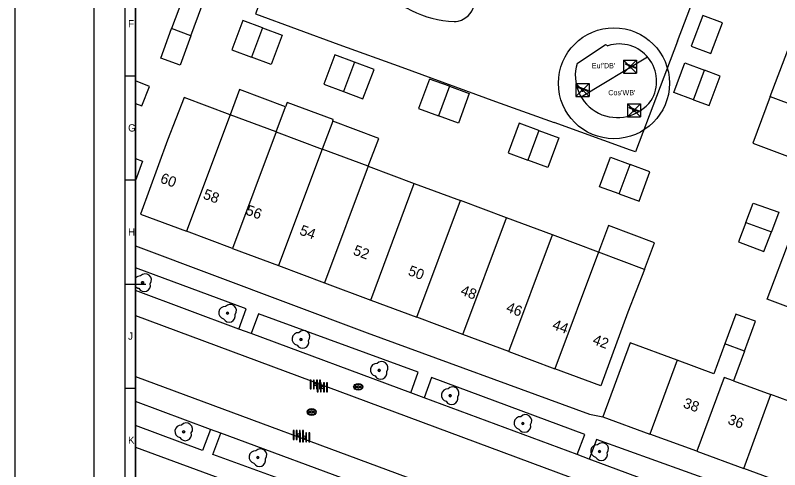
# Model space of a CAD drawing. Extents: x 192664 to 192925, y 446334 to 446521.
# Drawn here: x 192664.2 to 192737.6, y 446409.8 to 446453.5 of the extents above; entities that cross this region are included whole.
import ezdxf

# ---------------------------------------------------------------- set-up
doc = ezdxf.new("R2010")
doc.units = 0
for name, color, linetype in [('1010 viewport', 7, 'Continuous'), ('B-GV-KG-GRENS_WERKGRENS-G', 7, 'Continuous'), ('boom', 7, 'Continuous'), ('grens maaiveld', 7, 'Continuous'), ('huisnummerreeks BGT', 7, 'Continuous'), ('inspectie-   rioolput', 7, 'Continuous'), ('kant open verharding', 7, 'Continuous'), ('kant verharding', 7, 'Continuous'), ('kolk', 7, 'Continuous'), ('Luifel', 7, 'Continuous'), ('N-GV-GR-BEPLANTING-G', 7, 'Continuous'), ('pand op maaiveld vlak', 7, 'Continuous'), ('speelvoorziening', 7, 'Continuous'), ('TEKST', 7, 'Continuous'), ('V-GV-IE-MEUBILAIR_WEGMEUBILAIR_SPEELTOESTEL-G', 7, 'Continuous'), ('verkeerseiland - berm', 7, 'Continuous'), ('X-XX-AL-TEKENBLAD-S', 7, 'Continuous'), ('X-XX-AL-TEKENBLAD_KADER-G', 7, 'Continuous')]:
    doc.layers.add(name, color=color, linetype=linetype)

msp = doc.modelspace()

# ---------------------------------------------------------------- linework, layer by layer
at = {"layer": '1010 viewport'}
msp.add_lwpolyline([(192675.743, 446509.756), (192860.643, 446509.756), (192860.643, 446345.556), (192675.743, 446345.556)], close=True, dxfattribs=at)
at = {"layer": 'B-GV-KG-GRENS_WERKGRENS-G'}
msp.add_circle((192721.667, 446446.943), 5.327, dxfattribs=at)
at = {"layer": 'boom'}
msp.add_line((192675.743, 446428.235), (192675.743, 446427.429), dxfattribs=at)
for centre in [(192676.438, 446427.782), (192684.588, 446424.849), (192691.63, 446422.331), (192699.133, 446419.361), (192705.949, 446416.928), (192712.93, 446414.262), (192680.38, 446413.459), (192720.289, 446411.56), (192687.499, 446410.984)]:
    msp.add_circle(centre, 0.1, dxfattribs=at)
for centre, radius, start, end in [((192676.188, 446427.832), 0.6, 85.13702, 137.81973), ((192676.688, 446428.032), 0.6, 323.54458, 138.4658), ((192676.588, 446427.532), 0.6, 208.50578, 13.83556), ((192676.438, 446427.782), 0.1, 0, 180), ((192676.438, 446427.782), 0.1, 180, 0), ((192676.188, 446427.832), 0.6, 222.18027, 257.75442), ((192684.338, 446424.899), 0.6, 85.13702, 257.75442), ((192684.838, 446425.099), 0.6, 323.54458, 138.4658), ((192684.738, 446424.599), 0.6, 208.50578, 13.83556), ((192684.588, 446424.849), 0.1, 0, 180), ((192684.588, 446424.849), 0.1, 180, 0), ((192691.38, 446422.381), 0.6, 85.13702, 257.75442), ((192691.88, 446422.581), 0.6, 323.54458, 138.4658), ((192691.78, 446422.081), 0.6, 208.50578, 13.83556), ((192691.63, 446422.331), 0.1, 0, 180), ((192691.63, 446422.331), 0.1, 180, 0), ((192698.883, 446419.411), 0.6, 85.13702, 257.75442), ((192699.383, 446419.611), 0.6, 323.54458, 138.4658), ((192699.283, 446419.111), 0.6, 208.50578, 13.83556), ((192699.133, 446419.361), 0.1, 0, 180), ((192699.133, 446419.361), 0.1, 180, 0), ((192705.699, 446416.978), 0.6, 85.13702, 257.75442), ((192706.199, 446417.178), 0.6, 323.54458, 138.4658), ((192706.099, 446416.678), 0.6, 208.50578, 13.83556), ((192705.949, 446416.928), 0.1, 0, 180), ((192705.949, 446416.928), 0.1, 180, 0), ((192712.68, 446414.312), 0.6, 85.13702, 257.75442), ((192713.18, 446414.512), 0.6, 323.54458, 138.4658), ((192680.13, 446413.509), 0.6, 85.13702, 257.75442), ((192680.63, 446413.709), 0.6, 323.54458, 138.4658), ((192713.08, 446414.012), 0.6, 208.50578, 13.83556), ((192712.93, 446414.262), 0.1, 0, 180), ((192712.93, 446414.262), 0.1, 180, 0), ((192680.53, 446413.209), 0.6, 208.50578, 13.83556), ((192680.38, 446413.459), 0.1, 0, 180), ((192680.38, 446413.459), 0.1, 180, 0), ((192720.039, 446411.61), 0.6, 85.13702, 257.75442), ((192720.539, 446411.81), 0.6, 323.54458, 138.4658), ((192687.249, 446411.034), 0.6, 85.13702, 257.75442), ((192687.749, 446411.234), 0.6, 323.54458, 138.4658), ((192720.439, 446411.31), 0.6, 208.50578, 13.83556), ((192720.289, 446411.56), 0.1, 0, 180), ((192720.289, 446411.56), 0.1, 180, 0), ((192687.649, 446410.734), 0.6, 208.50578, 13.83556), ((192687.499, 446410.984), 0.1, 0, 180), ((192687.499, 446410.984), 0.1, 180, 0)]:
    msp.add_arc(centre, radius, start, end, dxfattribs=at)
at = {"layer": 'grens maaiveld'}
for p, q in [((192727.776, 446450.988), (192734.733, 446469.332)), ((192695.28, 446450.68), (192701.299, 446448.474))]:
    msp.add_line(p, q, dxfattribs=at)
for points in [[(192706.331, 446452.863), (192706.518, 446452.877), (192706.732, 446452.916), (192707.023, 446453.007), (192707.362, 446453.181), (192707.672, 446453.423), (192707.87, 446453.641), (192708.021, 446453.863), (192708.159, 446454.143), (192708.26, 446454.473), (192708.295, 446454.703), (192708.29, 446455.149), (192708.241, 446455.406), (192708.137, 446455.709), (192707.986, 446455.995), (192707.816, 446456.224), (192707.394, 446456.89), (192705.222, 446458.158), (192705.296, 446459.943), (192704.312, 446461.578), (192703.272, 446461.519), (192701.368, 446465.65), (192700.45, 446467.928), (192697.225, 446464.769)], [(192691.747, 446465.52), (192687.282, 446453.612), (192695.28, 446450.68)], [(192727.776, 446450.988), (192723.743, 446440.355), (192723.261, 446440.509), (192715.923, 446443.165)], [(192718.128, 446448.834), (192720.866, 446450.656), (192721.084, 446450.551)], [(192701.299, 446448.474), (192710.291, 446445.203), (192715.923, 446443.165)]]:
    msp.add_lwpolyline(points, dxfattribs=at)
for centre, radius, start, end in [((192706.69, 446462.573), 9.716, 166.93585, 267.88344), ((192722.168, 446447.137), 3.582, 328.76282, 107.61496), ((192721.99, 446447.676), 4.031, 163.30738, 323.51736)]:
    msp.add_arc(centre, radius, start, end, dxfattribs=at)
at = {"layer": 'inspectie-   rioolput'}
for p, q in [((192697.037, 446417.818), (192696.88, 446417.818)), ((192696.88, 446417.742), (192697.037, 446417.742)), ((192697.38, 446417.818), (192697.223, 446417.818)), ((192697.223, 446417.742), (192697.38, 446417.742)), ((192692.564, 446415.408), (192692.407, 446415.408)), ((192692.407, 446415.333), (192692.564, 446415.333)), ((192692.907, 446415.408), (192692.75, 446415.408)), ((192692.75, 446415.333), (192692.907, 446415.333))]:
    msp.add_line(p, q, dxfattribs=at)
for centre, radius, start, end in [((192696.88, 446417.78), 0.0375, 90, 270), ((192697.13, 446417.78), 0.1, 0, 180), ((192697.13, 446417.78), 0.1, 157.97569, 180), ((192697.13, 446417.78), 0.1, 180, 202.02431), ((192697.13, 446417.78), 0.1, 180, 0), ((192697.13, 446417.78), 0.1, 0, 22.02431), ((192697.13, 446417.78), 0.1, 337.97569, 0), ((192697.38, 446417.78), 0.0375, 270, 90), ((192692.407, 446415.37), 0.0375, 90, 270), ((192692.657, 446415.37), 0.1, 0, 180), ((192692.657, 446415.37), 0.1, 157.97569, 180), ((192692.657, 446415.37), 0.1, 180, 202.02431), ((192692.657, 446415.37), 0.1, 180, 0), ((192692.657, 446415.37), 0.1, 0, 22.02431), ((192692.657, 446415.37), 0.1, 337.97569, 0), ((192692.907, 446415.37), 0.0375, 270, 90)]:
    msp.add_arc(centre, radius, start, end, dxfattribs=at)
for centre, major_axis, ratio in [((192697.13, 446417.78), (-0.442, 0), 0.73911), ((192697.13, 446417.78), (-0.392, 0), 0.689655), ((192692.657, 446415.37), (-0.442, 0), 0.73911), ((192692.657, 446415.37), (-0.392, 0), 0.689655)]:
    msp.add_ellipse(centre, major_axis=major_axis, ratio=ratio, dxfattribs=at)
at = {"layer": 'kant open verharding'}
for points in [[(192675.743, 446431.332), (192697.987, 446422.959), (192719.324, 446415.141), (192720.614, 446414.897)], [(192675.743, 446411.995), (192713.029, 446398.263), (192714.204, 446397.83), (192714.097, 446397.514)]]:
    msp.add_lwpolyline(points, dxfattribs=at)
at = {"layer": 'kant verharding'}
for p, q in [((192675.743, 446424.623), (192733.082, 446403.313)), ((192686.85, 446422.89), (192685.668, 446423.329)), ((192675.743, 446418.762), (192731.114, 446398.266)), ((192703.446, 446416.734), (192702.166, 446417.209)), ((192683.929, 446413.333), (192682.95, 446413.694)), ((192719.304, 446410.835), (192718.14, 446411.268))]:
    msp.add_line(p, q, dxfattribs=at)
at = {"layer": 'kolk'}
for points in [[(192692.616, 446418.006), (192692.616, 446418.431), (192692.531, 446418.431), (192692.531, 446418.006), (192692.531, 446417.581), (192692.616, 446417.581)], [(192692.914, 446418.006), (192692.914, 446418.431), (192692.829, 446418.431), (192692.829, 446418.006), (192692.829, 446417.581), (192692.914, 446417.581)], [(192693.211, 446418.006), (192693.211, 446418.431), (192693.126, 446418.431), (192693.126, 446418.006), (192693.126, 446417.581), (192693.211, 446417.581)], [(192693.282, 446417.729), (192693.282, 446418.154), (192693.197, 446418.154), (192693.197, 446417.729), (192693.197, 446417.304), (192693.282, 446417.304)], [(192693.509, 446418.006), (192693.509, 446418.431), (192693.424, 446418.431), (192693.424, 446418.006), (192693.424, 446417.581), (192693.509, 446417.581)], [(192693.58, 446417.729), (192693.58, 446418.154), (192693.495, 446418.154), (192693.495, 446417.729), (192693.495, 446417.304), (192693.58, 446417.304)], [(192693.877, 446417.729), (192693.877, 446418.154), (192693.792, 446418.154), (192693.792, 446417.729), (192693.792, 446417.304), (192693.877, 446417.304)], [(192694.175, 446417.729), (192694.175, 446418.154), (192694.09, 446418.154), (192694.09, 446417.729), (192694.09, 446417.304), (192694.175, 446417.304)], [(192690.973, 446413.16), (192690.973, 446413.585), (192690.888, 446413.585), (192690.888, 446413.16), (192690.888, 446412.735), (192690.973, 446412.735)], [(192691.271, 446413.16), (192691.271, 446413.585), (192691.186, 446413.585), (192691.186, 446413.16), (192691.186, 446412.735), (192691.271, 446412.735)], [(192691.568, 446413.16), (192691.568, 446413.585), (192691.483, 446413.585), (192691.483, 446413.16), (192691.483, 446412.735), (192691.568, 446412.735)], [(192691.583, 446412.932), (192691.583, 446413.357), (192691.498, 446413.357), (192691.498, 446412.932), (192691.498, 446412.507), (192691.583, 446412.507)], [(192691.866, 446413.16), (192691.866, 446413.585), (192691.781, 446413.585), (192691.781, 446413.16), (192691.781, 446412.735), (192691.866, 446412.735)], [(192691.881, 446412.932), (192691.881, 446413.357), (192691.796, 446413.357), (192691.796, 446412.932), (192691.796, 446412.507), (192691.881, 446412.507)], [(192692.178, 446412.932), (192692.178, 446413.357), (192692.093, 446413.357), (192692.093, 446412.932), (192692.093, 446412.507), (192692.178, 446412.507)], [(192692.476, 446412.932), (192692.476, 446413.357), (192692.391, 446413.357), (192692.391, 446412.932), (192692.391, 446412.507), (192692.476, 446412.507)]]:
    msp.add_lwpolyline(points, close=True, dxfattribs=at)
for centre, start, end in [((192693.02, 446418.006), 0, 180), ((192693.02, 446418.006), 180, 0), ((192693.686, 446417.729), 0, 180), ((192693.686, 446417.729), 180, 0), ((192691.377, 446413.16), 0, 180), ((192691.377, 446413.16), 180, 0), ((192691.987, 446412.932), 0, 180), ((192691.987, 446412.932), 180, 0)]:
    msp.add_arc(centre, 0.1, start, end, dxfattribs=at)
at = {"layer": 'Luifel'}
for p, q in [((192689.258, 446442.274), (192690.161, 446444.691)), ((192694.676, 446443.3), (192693.675, 446440.623))]:
    msp.add_line(p, q, dxfattribs=at)
for points in [[(192729.308, 446445.356), (192730.801, 446444.796), (192731.861, 446447.624), (192730.368, 446448.184)], [(192690.161, 446444.691), (192685.743, 446446.341), (192684.84, 446443.924)], [(192694.676, 446443.3), (192694.73, 446443.445), (192690.312, 446445.096), (192690.161, 446444.691)], [(192698.093, 446438.972), (192699.094, 446441.649), (192694.676, 446443.3)], [(192724.599, 446429.067), (192725.554, 446431.622), (192721.136, 446433.273), (192720.181, 446430.718)]]:
    msp.add_lwpolyline(points, dxfattribs=at)
at = {"layer": 'N-GV-GR-BEPLANTING-G'}
msp.add_line((192718.512, 446445.637), (192724.889, 446449.467), dxfattribs=at)
msp.add_lwpolyline([(192718.128, 446448.834), (192720.866, 446450.656), (192721.084, 446450.551)], dxfattribs=at)
for centre, radius, start, end in [((192722.168, 446447.137), 3.582, 328.76282, 107.61496), ((192721.99, 446447.676), 4.031, 163.30738, 323.51736)]:
    msp.add_arc(centre, radius, start, end, dxfattribs=at)
at = {"layer": 'pand op maaiveld vlak'}
for p, q in [((192681.074, 446451.51), (192679.224, 446452.192)), ((192687.949, 446452.262), (192686.895, 446449.442)), ((192736.66, 446445.654), (192738.338, 446450.129)), ((192696.761, 446448.973), (192695.704, 446446.144)), ((192729.308, 446445.356), (192730.368, 446448.184)), ((192705.871, 446446.648), (192704.828, 446443.814)), ((192736.66, 446445.654), (192747.878, 446441.449)), ((192684.84, 446443.924), (192680.653, 446432.721)), ((192689.258, 446442.274), (192684.84, 446443.924)), ((192689.258, 446442.274), (192685.071, 446431.07)), ((192689.258, 446442.274), (192693.675, 446440.623)), ((192714.47, 446442.392), (192713.417, 446439.561)), ((192693.675, 446440.623), (192689.489, 446429.42)), ((192698.093, 446438.972), (192693.675, 446440.623)), ((192698.093, 446438.972), (192693.906, 446427.769)), ((192698.093, 446438.972), (192702.51, 446437.321)), ((192722.176, 446436.304), (192723.223, 446439.137)), ((192698.324, 446426.118), (192702.51, 446437.321)), ((192702.51, 446437.321), (192706.928, 446435.671)), ((192702.742, 446424.467), (192706.928, 446435.671)), ((192711.346, 446434.02), (192706.928, 446435.671)), ((192707.159, 446422.816), (192711.346, 446434.02)), ((192715.763, 446432.369), (192711.346, 446434.02)), ((192734.324, 446433.557), (192736.775, 446432.672)), ((192685.071, 446431.07), (192680.653, 446432.721)), ((192711.577, 446421.166), (192715.763, 446432.369)), ((192720.181, 446430.718), (192715.763, 446432.369)), ((192685.071, 446431.07), (192689.489, 446429.42)), ((192720.181, 446430.718), (192715.995, 446419.515)), ((192724.599, 446429.067), (192720.181, 446430.718)), ((192689.489, 446429.42), (192693.906, 446427.769)), ((192693.906, 446427.769), (192698.324, 446426.118)), ((192698.324, 446426.118), (192702.742, 446424.467)), ((192707.159, 446422.816), (192702.742, 446424.467)), ((192711.577, 446421.166), (192707.159, 446422.816)), ((192734.182, 446421.216), (192732.296, 446421.908)), ((192711.577, 446421.166), (192715.995, 446419.515)), ((192734.182, 446421.216), (192733.13, 446418.353)), ((192727.725, 446420.338), (192725.118, 446413.242)), ((192733.13, 446418.353), (192736.734, 446417.029)), ((192734.126, 446409.932), (192736.734, 446417.029)), ((192741.127, 446415.414), (192736.734, 446417.029)), ((192720.614, 446414.897), (192725.118, 446413.242)), ((192729.622, 446411.587), (192725.118, 446413.242)), ((192729.622, 446411.587), (192734.126, 446409.932))]:
    msp.add_line(p, q, dxfattribs=at)
for points in [[(192681.074, 446451.51), (192682.119, 446454.348), (192680.269, 446455.029), (192679.224, 446452.192)], [(192729.085, 446450.517), (192730.979, 446449.814), (192732.074, 446452.735), (192730.18, 446453.439), (192729.085, 446450.517)], [(192687.949, 446452.262), (192686.068, 446452.972), (192685.011, 446450.143), (192686.895, 446449.442)], [(192681.074, 446451.51), (192680.029, 446448.672), (192678.178, 446449.354), (192679.224, 446452.192)], [(192687.949, 446452.262), (192689.829, 446451.552), (192688.778, 446448.741), (192686.895, 446449.442)], [(192696.761, 446448.973), (192694.879, 446449.681), (192693.822, 446446.852), (192695.704, 446446.144)], [(192695.704, 446446.144), (192697.585, 446445.436), (192698.642, 446448.265), (192696.761, 446448.973)], [(192729.308, 446445.356), (192727.415, 446446.06), (192728.475, 446448.888), (192730.368, 446448.184)], [(192675.743, 446445.002), (192676.376, 446444.757), (192677.105, 446446.641), (192675.743, 446447.168)], [(192705.871, 446446.648), (192703.964, 446447.349), (192702.921, 446444.515), (192704.828, 446443.814)], [(192705.871, 446446.648), (192707.778, 446445.946), (192706.735, 446443.112), (192704.828, 446443.814)], [(192684.84, 446443.924), (192680.423, 446445.575), (192678.816, 446441.474), (192676.236, 446434.372), (192680.653, 446432.721)], [(192736.66, 446445.654), (192734.983, 446441.178), (192739.086, 446439.641), (192746.201, 446436.974), (192747.878, 446441.449)], [(192714.47, 446442.392), (192712.567, 446443.096), (192711.511, 446440.267), (192713.417, 446439.561)], [(192714.47, 446442.392), (192716.372, 446441.687), (192715.323, 446438.855), (192713.417, 446439.561)], [(192675.743, 446439.714), (192676.434, 446439.457), (192675.743, 446437.601)], [(192722.176, 446436.304), (192720.279, 446437.005), (192721.326, 446439.838), (192723.223, 446439.137)], [(192722.176, 446436.304), (192724.072, 446435.603), (192725.119, 446438.436), (192723.223, 446439.137)], [(192734.324, 446433.557), (192735.013, 446435.41), (192737.504, 446434.553), (192736.775, 446432.672)], [(192734.324, 446433.557), (192733.634, 446431.703), (192736.045, 446430.79), (192736.775, 446432.672)], [(192744.037, 446423.324), (192736.376, 446426.21), (192738.567, 446432.027)], [(192724.599, 446429.067), (192722.99, 446424.96), (192720.412, 446417.864), (192715.995, 446419.515)], [(192734.182, 446421.216), (192735.234, 446424.078), (192734.332, 446424.409), (192733.348, 446424.771), (192732.296, 446421.908)], [(192727.725, 446420.338), (192723.221, 446421.993), (192720.614, 446414.897)], [(192732.296, 446421.908), (192731.243, 446419.044), (192727.725, 446420.338)], [(192733.13, 446418.353), (192732.229, 446418.684), (192729.622, 446411.587)], [(192738.776, 446408.675), (192738.63, 446408.277), (192734.126, 446409.932)]]:
    msp.add_lwpolyline(points, dxfattribs=at)
at = {"layer": 'speelvoorziening'}
for p, q in [((192722.794, 446448.767), (192723.156, 446448.627)), ((192723.737, 446448.466), (192722.816, 446448.822)), ((192723.336, 446448.557), (192723.716, 446448.41)), ((192718.222, 446446.547), (192718.584, 446446.407)), ((192719.165, 446446.246), (192718.244, 446446.602)), ((192718.764, 446446.337), (192719.144, 446446.19)), ((192723.149, 446444.575), (192723.511, 446444.435)), ((192724.092, 446444.274), (192723.171, 446444.63)), ((192723.691, 446444.365), (192724.071, 446444.218))]:
    msp.add_line(p, q, dxfattribs=at)
for centre in [(192723.221, 446448.527), (192718.649, 446446.307), (192723.576, 446444.335)]:
    msp.add_circle(centre, 0.1, dxfattribs=at)
for centre, radius, start, end in [((192722.805, 446448.795), 0.0297, 68.83874, 248.83874), ((192723.221, 446448.527), 0.119, 123.04996, 14.62752), ((192723.221, 446448.527), 0.1, 0, 180), ((192723.221, 446448.527), 0.1, 180, 0), ((192723.726, 446448.438), 0.0297, 248.83874, 68.83874), ((192718.233, 446446.575), 0.0297, 68.83874, 248.83874), ((192718.649, 446446.307), 0.119, 123.04996, 14.62752), ((192718.649, 446446.307), 0.1, 0, 180), ((192718.649, 446446.307), 0.1, 180, 0), ((192719.154, 446446.218), 0.0297, 248.83874, 68.83874), ((192723.16, 446444.603), 0.0297, 68.83874, 248.83874), ((192723.576, 446444.335), 0.119, 123.04996, 14.62752), ((192723.576, 446444.335), 0.1, 0, 180), ((192723.576, 446444.335), 0.1, 180, 0), ((192724.081, 446444.246), 0.0297, 248.83874, 68.83874)]:
    msp.add_arc(centre, radius, start, end, dxfattribs=at)
at = {"layer": 'V-GV-IE-MEUBILAIR_WEGMEUBILAIR_SPEELTOESTEL-G'}
for p, q in [((192722.596, 446449.152), (192723.846, 446449.152)), ((192722.596, 446449.152), (192722.596, 446447.902)), ((192722.596, 446449.152), (192723.846, 446447.902)), ((192722.596, 446447.902), (192723.846, 446449.152)), ((192723.846, 446449.152), (192723.846, 446447.902)), ((192722.596, 446447.902), (192723.846, 446447.902)), ((192718.024, 446446.932), (192719.274, 446446.932)), ((192718.024, 446446.932), (192718.024, 446445.682)), ((192718.024, 446446.932), (192719.274, 446445.682)), ((192718.024, 446445.682), (192719.274, 446446.932)), ((192719.274, 446446.932), (192719.274, 446445.682)), ((192718.024, 446445.682), (192719.274, 446445.682)), ((192722.951, 446444.96), (192724.201, 446444.96)), ((192722.951, 446444.96), (192722.951, 446443.71)), ((192722.951, 446444.96), (192724.201, 446443.71)), ((192722.951, 446443.71), (192724.201, 446444.96)), ((192724.201, 446444.96), (192724.201, 446443.71)), ((192722.951, 446443.71), (192724.201, 446443.71))]:
    msp.add_line(p, q, dxfattribs=at)
at = {"layer": 'verkeerseiland - berm'}
for p, q in [((192685.668, 446423.329), (192675.743, 446427.021)), ((192702.166, 446417.209), (192686.85, 446422.89)), ((192718.14, 446411.268), (192703.446, 446416.734)), ((192682.95, 446413.694), (192675.743, 446416.376)), ((192699.029, 446407.759), (192683.929, 446413.333)), ((192730.661, 446406.636), (192719.304, 446410.835))]:
    msp.add_line(p, q, dxfattribs=at)
for points in [[(192685.668, 446423.329), (192686.387, 446425.276), (192675.743, 446429.208)], [(192702.166, 446417.209), (192702.891, 446419.191), (192687.553, 446424.809), (192686.85, 446422.89)], [(192718.14, 446411.268), (192718.857, 446413.191), (192704.17, 446418.672), (192703.446, 446416.734)], [(192682.95, 446413.694), (192682.193, 446411.661), (192675.743, 446414.063)], [(192699.029, 446407.759), (192698.296, 446405.758), (192683.182, 446411.296), (192683.929, 446413.333)], [(192730.661, 446406.636), (192731.377, 446408.627), (192719.987, 446412.729), (192719.304, 446410.835)]]:
    msp.add_lwpolyline(points, dxfattribs=at)
at = {"layer": 'X-XX-AL-TEKENBLAD-S'}
for p, q in [((192671.743, 446511.756), (192671.743, 446343.556)), ((192674.743, 446510.756), (192674.743, 446344.556)), ((192674.743, 446447.656), (192675.743, 446447.656)), ((192674.743, 446437.656), (192675.743, 446437.656)), ((192674.743, 446417.656), (192675.743, 446417.656))]:
    msp.add_line(p, q, dxfattribs=at)
msp.add_lwpolyline([(192675.743, 446345.556), (192907.543, 446345.556), (192907.543, 446509.756), (192675.743, 446509.756)], close=True, dxfattribs=at)
msp.add_lwpolyline([(192674.743, 446427.656), (192676.743, 446427.656)], dxfattribs=at)
at = {"layer": 'X-XX-AL-TEKENBLAD_KADER-G'}
msp.add_lwpolyline([(192664.22, 446520.974), (192925.029, 446520.974), (192925.029, 446333.894), (192664.22, 446333.894)], close=True, dxfattribs=at)

# ---------------------------------------------------------------- texts
at = {"layer": 'huisnummerreeks BGT'}
for s, rotation, p in [('60', 339.6, (192678.052, 446437.428)), ('58', 339.6, (192682.167, 446435.891)), ('56', 339.6, (192686.258, 446434.362)), ('54', 339.6, (192691.419, 446432.434)), ('52', 339.6, (192696.568, 446430.51)), ('50', 339.6, (192701.832, 446428.543)), ('48', 339.6, (192706.872, 446426.659)), ('46', 339.6, (192711.242, 446425.027)), ('44', 339.6, (192715.674, 446423.37)), ('42', 339.6, (192719.542, 446421.925)), ('38', 339.9, (192728.228, 446415.827)), ('36', 339.9, (192732.51, 446414.253))]:
    msp.add_text(s, height=1, rotation=rotation, dxfattribs=at).set_placement(p)
at = {"layer": 'TEKST'}
for s, p in [("Euf'DB'", (192719.535, 446448.38)), ("Cos'WB'", (192721.123, 446445.792))]:
    msp.add_text(s, height=0.5, dxfattribs=at).set_placement(p)
at = {"layer": 'X-XX-AL-TEKENBLAD-S'}
for s, p in [('F', (192675.043, 446452.306)), ('G', (192675.043, 446442.306)), ('H', (192675.043, 446432.306)), ('J', (192675.043, 446422.306)), ('K', (192675.043, 446412.306))]:
    msp.add_text(s, height=0.7, dxfattribs=at).set_placement(p)

doc.saveas('drawing.dxf')
